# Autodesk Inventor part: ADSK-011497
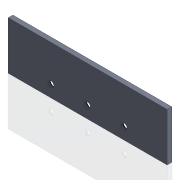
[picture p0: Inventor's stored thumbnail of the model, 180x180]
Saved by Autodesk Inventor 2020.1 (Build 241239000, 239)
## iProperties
Created: 2000-02
Part Number: ADSK-011497
Material: Pearson Stainless Steel
Description: PLT-03,FS,CP,01,065,020,VVV,PLATE,FACE,MANDREL
Document SubType Name: Modeling
Designer: sspink
Density: 8.03 g/cm^3
Appearance: Pearson-Stainless
Mass: 309.147 g
Surface Area: 185.937 cm^2
Volume: 38.499 cm^3
Control State: 0
Master: False
Checked Out: False
Shininess: 57.0
Length Units: 11269
Angle Units: 11279
Time Units: 11290
Mass Units: 11283
Length Display Precision: 3
Angle Display Precision: 2
Compacted: True
Cutlength: 6.5
Material Desc: FLAT,S/S,0.188 X 2.00
Material_number: A089267
Dimensions: 165x50x4,8 mm
Mass: 0,309 kg
Density: 8.03
Volumn: 38.709395290759396
Area: 188.2319187956656
PropertySet Name: Model Information
Author: sspink
Revision Number: -
Title: PLT-03,FS,CP,01,065,020,VVV,PLATE,FACE,MANDREL
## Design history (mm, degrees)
node "Hole1" dims "d9" = 5.5, "d10" = 12.5, "d11" = 6.35, "d12" = 90 deg, "d13" = 19.05, "d14" = 118 deg, "d21" = 6
  sketch "Sketch2"
    geometry: L1 (0, 0)-(-165, 0) reference; L2 (-44.5, 12.5)-(-120.5, 12.5); 3 further points
    constraints: 2 end point, 2 horizontal alignment, 2 midpoint, 1 coincident, 1 horizontal, 1 vertical alignment
    dimensions: "d19" = 12.5 distance from line of L2.end L1; "d20" = 76 distance of L2.start L2.end
node "Solide1"
  node "Extrusion1" dims "d2" = 4.7625, "d3" = 0
sketch "Sketch1"
  geometry: L1 (0, 0)-(165, 0); L2 (165, 0)-(165, 50); L3 (165, 50)-(0, 50); L4 (0, 50)-(0, 0)
  constraints: 8 end point, 2 parallel, 1 horizontal, 1 perpendicular
  dimensions: "d0" = 50 distance between parallel lines of L1 L3; "d1" = 165 distance between parallel lines of L2 L4
node "Corps solides"
node "Corps surfaciques"
